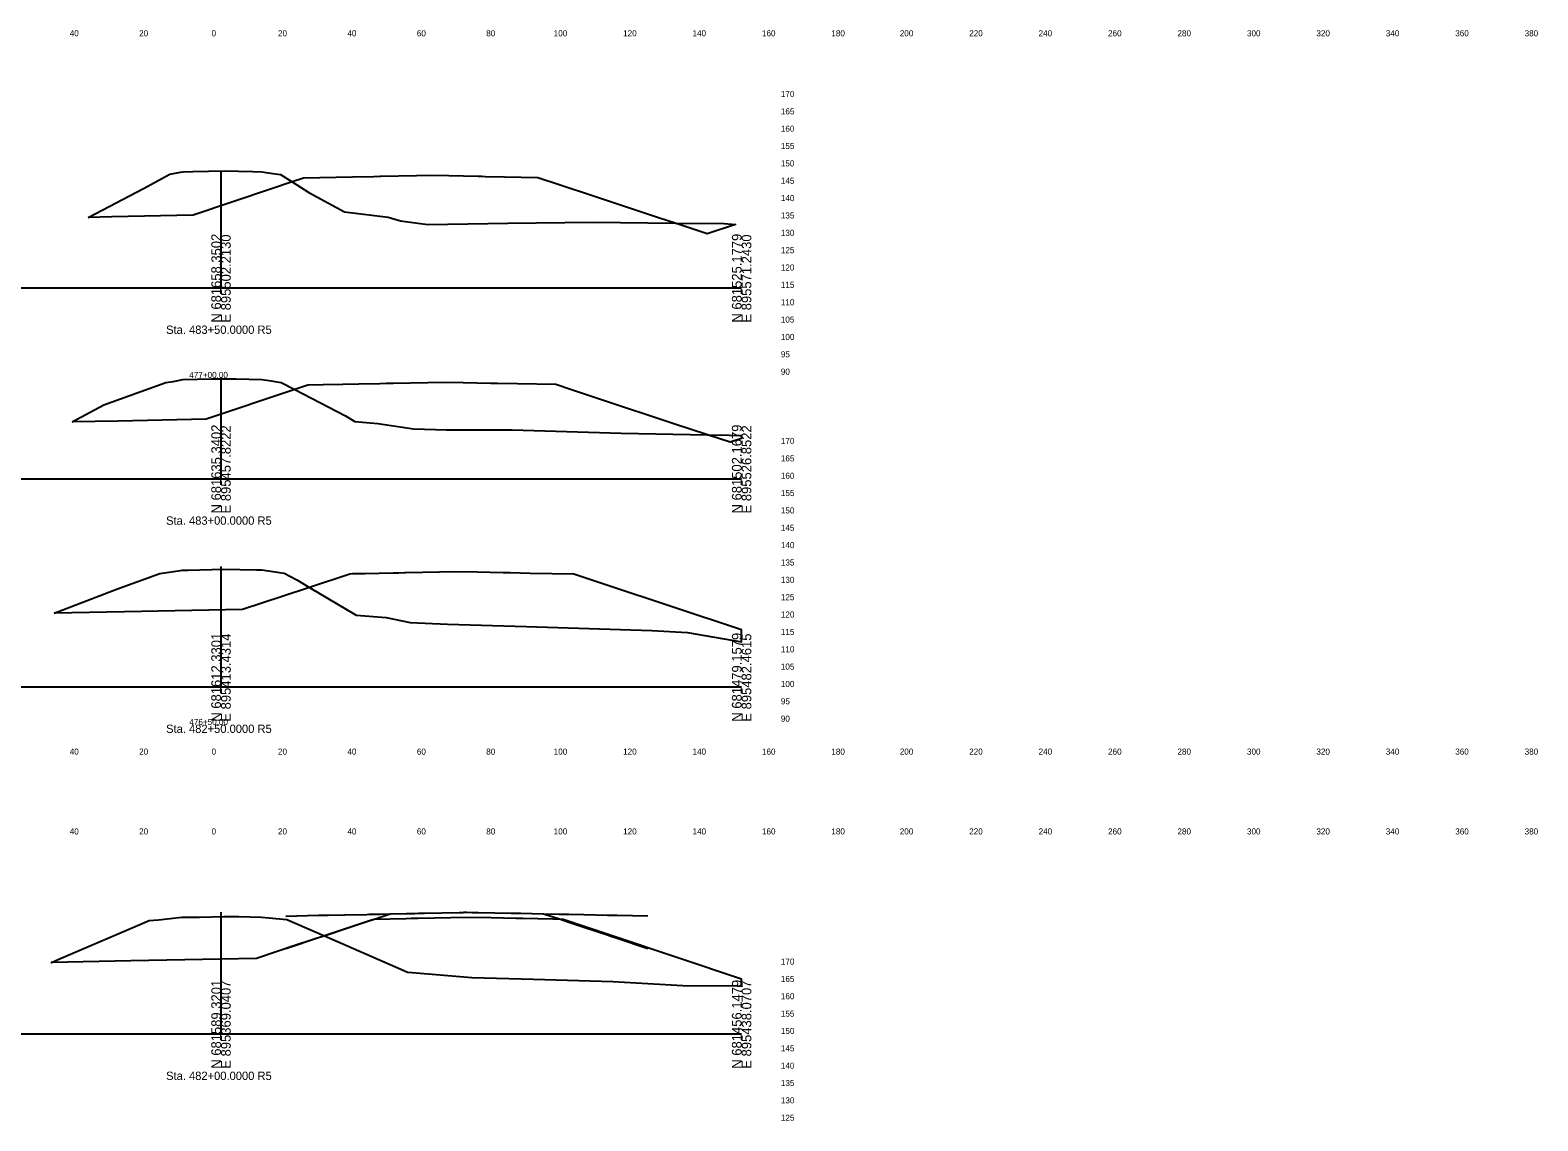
# Model space of a CAD drawing. Extents: x 21059 to 22955, y 6470 to 17494.
# Drawn here: x 21589.8 to 22024.2, y 11659.8 to 11974.1 of the extents above; entities that cross this region are included whole.
import ezdxf

# ---------------------------------------------------------------- set-up
doc = ezdxf.new("R2010")
doc.units = 0
for name, color, linetype in [('Draft_XS_Grid', 7, 'Continuous'), ('Draft_XS_Text', 7, 'Continuous'), ('DTM CONTOURS_MAJOR', 7, 'Continuous'), ('SLOPE_STAKES_FILL', 7, 'Continuous'), ('X_PROFILES_1', 7, 'Continuous'), ('XS_P_GROUND_B', 7, 'Continuous'), ('XS_P_TX_CLEARZONE', 7, 'Continuous'), ('XS_SHEET_EW_TX_VOLUME', 7, 'Continuous')]:
    doc.layers.add(name, color=color, linetype=linetype)

msp = doc.modelspace()

# ---------------------------------------------------------------- linework, layer by layer
at = {"layer": 'DTM CONTOURS_MAJOR'}
for p, q in [((21644.84, 11899.84), (21644.84, 11933.7)), ((21494.84, 11899.84), (21644.84, 11899.84)), ((21644.84, 11899.84), (21794.84, 11899.84)), ((21644.84, 11844.84), (21644.84, 11874.1)), ((21494.84, 11844.84), (21644.84, 11844.84)), ((21644.84, 11844.84), (21794.84, 11844.84)), ((21644.84, 11784.84), (21644.84, 11819.51)), ((21494.84, 11784.84), (21644.84, 11784.84)), ((21644.84, 11784.84), (21794.84, 11784.84)), ((21644.84, 11684.84), (21644.84, 11719.92)), ((21494.84, 11684.84), (21644.84, 11684.84)), ((21644.84, 11684.84), (21794.84, 11684.84))]:
    msp.add_line(p, q, dxfattribs=at)
at = {"layer": 'XS_P_TX_CLEARZONE'}
for points in [[(21663.47, 11709.45), (21672.96, 11712.6), (21673.92, 11712.93), (21675.73, 11713.53), (21680.54, 11715.13), (21686.83, 11717.22), (21687.4, 11717.41), (21689.6, 11718.15), (21690.67, 11718.5), (21693.55, 11719.46), (21698.32, 11719.56), (21700.7, 11719.61), (21701.73, 11719.63), (21703.48, 11719.67), (21713.43, 11719.87), (21714.58, 11719.89), (21714.7, 11719.9), (21715.71, 11719.92), (21717.17, 11719.89), (21717.35, 11719.89), (21719, 11719.85), (21728.45, 11719.67), (21729.49, 11719.65), (21731.22, 11719.62), (21737.77, 11719.49), (21742.32, 11717.98), (21744.47, 11717.27), (21745.09, 11717.06), (21749.37, 11715.64), (21756.19, 11713.38), (21757.18, 11713.05), (21758.96, 11712.46), (21767.85, 11709.51)], [(21663.47, 11718.84), (21672.96, 11719.04), (21673.92, 11719.06), (21675.73, 11719.1), (21680.54, 11719.2), (21686.83, 11719.32), (21687.4, 11719.34), (21689.6, 11719.38), (21690.67, 11719.4), (21693.55, 11719.46), (21698.32, 11719.56), (21700.7, 11719.61), (21701.73, 11719.63), (21703.48, 11719.67), (21713.43, 11719.87), (21714.58, 11719.89), (21714.7, 11719.9), (21715.71, 11719.92), (21717.17, 11719.89), (21717.35, 11719.89), (21719, 11719.85), (21728.45, 11719.67), (21729.49, 11719.65), (21731.22, 11719.62), (21737.77, 11719.49), (21742.32, 11719.4), (21744.47, 11719.36), (21745.09, 11719.35), (21749.37, 11719.27), (21756.19, 11719.13), (21757.18, 11719.12), (21758.96, 11719.08), (21767.85, 11718.91)], [(21663.47, 11709.45), (21672.96, 11712.6), (21673.92, 11712.93), (21675.73, 11713.53), (21680.54, 11715.13), (21686.83, 11717.22), (21687.4, 11717.41), (21689.6, 11718.15), (21690.67, 11718.5), (21693.55, 11719.46), (21698.32, 11719.56), (21700.7, 11719.61), (21701.73, 11719.63), (21703.48, 11719.67), (21713.43, 11719.87), (21714.58, 11719.89), (21714.7, 11719.9), (21715.71, 11719.92), (21717.17, 11719.89), (21717.35, 11719.89), (21719, 11719.85), (21728.45, 11719.67), (21729.49, 11719.65), (21731.22, 11719.62), (21737.77, 11719.49), (21742.32, 11717.98), (21744.47, 11717.27), (21745.09, 11717.06), (21749.37, 11715.64), (21756.19, 11713.38), (21757.18, 11713.05), (21758.96, 11712.46), (21767.85, 11709.51)], [(21663.47, 11718.84), (21672.96, 11719.04), (21673.92, 11719.06), (21675.73, 11719.1), (21680.54, 11719.2), (21686.83, 11719.32), (21687.4, 11719.34), (21689.6, 11719.38), (21690.67, 11719.4), (21693.55, 11719.46), (21698.32, 11719.56), (21700.7, 11719.61), (21701.73, 11719.63), (21703.48, 11719.67), (21713.43, 11719.87), (21714.58, 11719.89), (21714.7, 11719.9), (21715.71, 11719.92), (21717.17, 11719.89), (21717.35, 11719.89), (21719, 11719.85), (21728.45, 11719.67), (21729.49, 11719.65), (21731.22, 11719.62), (21737.77, 11719.49), (21742.32, 11719.4), (21744.47, 11719.36), (21745.09, 11719.35), (21749.37, 11719.27), (21756.19, 11719.13), (21757.18, 11719.12), (21758.96, 11719.08), (21767.85, 11718.91)]]:
    msp.add_lwpolyline(points, dxfattribs=at)
at = {"layer": 'XS_SHEET_EW_TX_VOLUME'}
for points in [[(21606.59, 11920.17), (21622.54, 11928.44), (21630.1, 11932.59), (21633.21, 11933.21), (21633.89, 11933.33), (21636.73, 11933.39), (21645.78, 11933.57), (21654, 11933.35), (21656.58, 11933.28), (21660.41, 11932.74), (21662, 11932.48), (21665.35, 11930.37), (21659.35, 11928.36), (21636.81, 11920.83), (21613.4, 11920.32)], [(21665.35, 11930.37), (21670.15, 11927.33), (21680.43, 11921.77), (21693.01, 11920.22), (21696.54, 11919.12), (21704.47, 11918.11), (21727.52, 11918.45), (21752.08, 11918.74), (21775.64, 11918.5), (21771.17, 11919.98), (21752.12, 11926.29), (21742.23, 11929.56), (21736.11, 11931.59), (21726.49, 11931.78), (21720.91, 11931.89), (21719.99, 11931.9), (21718.91, 11931.92), (21710.48, 11932.09), (21704.87, 11932.2), (21701.15, 11932.12), (21690.84, 11931.91), (21690.61, 11931.91), (21688.83, 11931.87), (21682.76, 11931.74), (21668.61, 11931.46)], [(21775.64, 11918.5), (21789.81, 11918.35), (21793.1, 11918.14), (21784.91, 11915.43)], [(21601.94, 11861.21), (21611.03, 11866.13), (21628.94, 11872.56), (21631.04, 11872.87), (21633.87, 11873.43), (21642.08, 11873.59), (21645.75, 11873.68), (21649.17, 11873.62), (21656.6, 11873.42), (21658.68, 11873.11), (21662.13, 11872.62), (21666.1, 11870.55), (21640.52, 11862.01), (21615.2, 11861.48)], [(21666.1, 11870.55), (21680.74, 11862.94), (21683.41, 11861.36), (21690.04, 11860.78), (21700.32, 11859.26), (21709.79, 11858.94), (21728.77, 11858.95), (21760.15, 11857.97), (21785.01, 11857.49), (21775.3, 11860.7), (21753.92, 11867.78), (21745.52, 11870.57), (21741.31, 11871.96), (21730.22, 11872.17), (21724.53, 11872.28), (21723.65, 11872.3), (21722.52, 11872.32), (21714.56, 11872.48), (21708.49, 11872.6), (21704.46, 11872.51), (21694.45, 11872.31), (21694.17, 11872.3), (21692.44, 11872.27), (21690.6, 11872.23), (21684.56, 11872.1), (21679.98, 11872.01), (21674.26, 11871.89), (21669.84, 11871.8)], [(21785.01, 11857.49), (21791.28, 11857.36), (21794.84, 11857.32), (21794.84, 11856.44), (21791.51, 11855.34)], [(21596.78, 11806.12), (21615.05, 11813.14), (21627.25, 11817.52), (21633.12, 11818.38), (21633.69, 11818.49), (21635.35, 11818.53), (21645.55, 11818.77), (21655.08, 11818.59), (21656.57, 11818.55), (21662.33, 11817.7), (21663.01, 11817.61), (21666.68, 11815.7), (21670.33, 11813.54), (21662.42, 11810.92), (21651.05, 11807.16), (21617, 11806.51)], [(21670.33, 11813.54), (21683.81, 11805.57), (21692.4, 11804.82), (21699.3, 11803.44), (21710.11, 11802.98), (21732.87, 11802.24), (21768.98, 11801.07), (21779.26, 11800.51), (21794.84, 11797.87), (21794.84, 11801.34), (21755.73, 11814.29), (21746.5, 11817.34), (21733.88, 11817.58), (21728.14, 11817.7), (21727.32, 11817.71), (21726.14, 11817.73), (21718.63, 11817.88), (21712.1, 11818.01), (21707.77, 11817.92), (21698.06, 11817.72), (21697.74, 11817.71), (21696.06, 11817.68), (21694.47, 11817.64), (21686.36, 11817.48), (21682.74, 11817.4), (21681.97, 11817.39)], [(21595.97, 11705.49), (21598.13, 11706.38), (21624.11, 11717.5), (21626.84, 11717.77), (21633.59, 11718.52), (21638.65, 11718.53), (21645.64, 11718.7), (21650.02, 11718.66), (21656.54, 11718.54), (21663.78, 11717.82), (21663.83, 11717.82), (21674.63, 11713.12), (21666.73, 11710.5), (21655.06, 11706.62), (21618.81, 11705.93)], [(21674.63, 11713.12), (21696.64, 11703.55), (21698.59, 11702.67), (21699.94, 11702.54), (21717.12, 11701.14), (21734.91, 11700.67), (21757.75, 11699.94), (21777.9, 11698.82), (21793.52, 11698.7), (21794.84, 11698.62), (21794.84, 11700.63), (21757.53, 11713.16), (21743.46, 11717.88), (21740.45, 11717.94), (21731.76, 11718.11), (21730.99, 11718.12), (21729.75, 11718.15), (21722.7, 11718.28), (21715.71, 11718.42), (21711.08, 11718.32), (21701.68, 11718.13), (21701.3, 11718.12), (21699.67, 11718.09), (21698.15, 11718.06), (21688.9, 11717.87), (21688.17, 11717.62)], [(21595.92, 11705.49), (21595.92, 11705.47), (21595.97, 11705.49)]]:
    msp.add_lwpolyline(points, close=True, dxfattribs=at)

# ---------------------------------------------------------------- texts
at = {"layer": 'Draft_XS_Grid'}
for s, p in [('  170  ', (21804.84, 11954.84)), ('  165  ', (21804.84, 11949.84)), ('  160  ', (21804.84, 11944.84)), ('  155  ', (21804.84, 11939.84)), ('  150  ', (21804.84, 11934.84)), ('  145  ', (21804.84, 11929.84)), ('  140  ', (21804.84, 11924.84)), ('  135  ', (21804.84, 11919.84)), ('  130  ', (21804.84, 11914.84)), ('  125  ', (21804.84, 11909.84)), ('  120  ', (21804.84, 11904.84)), ('  115  ', (21804.84, 11899.84)), ('  110  ', (21804.84, 11894.84)), ('  105  ', (21804.84, 11889.84)), ('  100  ', (21804.84, 11884.84)), ('  95  ', (21804.84, 11879.84)), ('  90  ', (21804.84, 11874.84)), ('  170  ', (21804.84, 11854.84)), ('  165  ', (21804.84, 11849.84)), ('  160  ', (21804.84, 11844.84)), ('  155  ', (21804.84, 11839.84)), ('  150  ', (21804.84, 11834.84)), ('  145  ', (21804.84, 11829.84)), ('  140  ', (21804.84, 11824.84)), ('  135  ', (21804.84, 11819.84)), ('  130  ', (21804.84, 11814.84)), ('  125  ', (21804.84, 11809.84)), ('  120  ', (21804.84, 11804.84)), ('  115  ', (21804.84, 11799.84)), ('  110  ', (21804.84, 11794.84)), ('  105  ', (21804.84, 11789.84)), ('  100  ', (21804.84, 11784.84)), ('  95  ', (21804.84, 11779.84)), ('  90  ', (21804.84, 11774.84)), ('  170  ', (21804.84, 11704.84)), ('  165  ', (21804.84, 11699.84)), ('  160  ', (21804.84, 11694.84)), ('  155  ', (21804.84, 11689.84)), ('  150  ', (21804.84, 11684.84)), ('  145  ', (21804.84, 11679.84)), ('  140  ', (21804.84, 11674.84)), ('  135  ', (21804.84, 11669.84)), ('  130  ', (21804.84, 11664.84)), ('  125  ', (21804.84, 11659.84))]:
    msp.add_text(s, height=1.75, dxfattribs=at).set_placement(p)
at = {"layer": 'Draft_XS_Text'}
for s, p in [('  40  ', (21599.95, 11972.34)), ('  20  ', (21619.95, 11972.34)), ('  0  ', (21640.81, 11972.34)), ('  0  ', (21640.81, 11972.34)), ('  20  ', (21659.95, 11972.34)), ('  40  ', (21679.95, 11972.34)), ('  60  ', (21699.97, 11972.34)), ('  80  ', (21719.95, 11972.34)), ('  100  ', (21739.39, 11972.34)), ('  120  ', (21759.39, 11972.34)), ('  140  ', (21779.39, 11972.34)), ('  160  ', (21799.4, 11972.34)), ('  180  ', (21819.39, 11972.34)), ('  200  ', (21839.1, 11972.34)), ('  220  ', (21859.1, 11972.34)), ('  240  ', (21879.1, 11972.34)), ('  260  ', (21899.11, 11972.34)), ('  280  ', (21919.1, 11972.34)), ('  300  ', (21939.13, 11972.34)), ('  320  ', (21959.13, 11972.34)), ('  340  ', (21979.13, 11972.34)), ('  360  ', (21999.14, 11972.34)), ('  380  ', (22019.13, 11972.34)), ('  40  ', (21599.95, 11765.34)), ('  20  ', (21619.95, 11765.34)), ('  0  ', (21640.81, 11765.34)), ('  0  ', (21640.81, 11765.34)), ('  20  ', (21659.95, 11765.34)), ('  40  ', (21679.95, 11765.34)), ('  60  ', (21699.97, 11765.34)), ('  80  ', (21719.95, 11765.34)), ('  100  ', (21739.39, 11765.34)), ('  120  ', (21759.39, 11765.34)), ('  140  ', (21779.39, 11765.34)), ('  160  ', (21799.4, 11765.34)), ('  180  ', (21819.39, 11765.34)), ('  200  ', (21839.1, 11765.34)), ('  220  ', (21859.1, 11765.34)), ('  240  ', (21879.1, 11765.34)), ('  260  ', (21899.11, 11765.34)), ('  280  ', (21919.1, 11765.34)), ('  300  ', (21939.13, 11765.34)), ('  320  ', (21959.13, 11765.34)), ('  340  ', (21979.13, 11765.34)), ('  360  ', (21999.14, 11765.34)), ('  380  ', (22019.13, 11765.34)), ('  40  ', (21599.95, 11742.34)), ('  20  ', (21619.95, 11742.34)), ('  0  ', (21640.81, 11742.34)), ('  0  ', (21640.81, 11742.34)), ('  20  ', (21659.95, 11742.34)), ('  40  ', (21679.95, 11742.34)), ('  60  ', (21699.97, 11742.34)), ('  80  ', (21719.95, 11742.34)), ('  100  ', (21739.39, 11742.34)), ('  120  ', (21759.39, 11742.34)), ('  140  ', (21779.39, 11742.34)), ('  160  ', (21799.4, 11742.34)), ('  180  ', (21819.39, 11742.34)), ('  200  ', (21839.1, 11742.34)), ('  220  ', (21859.1, 11742.34)), ('  240  ', (21879.1, 11742.34)), ('  260  ', (21899.11, 11742.34)), ('  280  ', (21919.1, 11742.34)), ('  300  ', (21939.13, 11742.34)), ('  320  ', (21959.13, 11742.34)), ('  340  ', (21979.13, 11742.34)), ('  360  ', (21999.14, 11742.34)), ('  380  ', (22019.13, 11742.34))]:
    msp.add_text(s, height=1.75, dxfattribs=at).set_placement(p)
at = {"layer": 'DTM CONTOURS_MAJOR'}
for s, p in [('N 681658.3502', (21644.84, 11889.84)), ('E 895502.2130', (21647.64, 11889.84)), ('N 681525.1779', (21794.84, 11889.84)), ('E 895571.2430', (21797.64, 11889.84)), ('N 681635.3402', (21644.84, 11834.84)), ('E 895457.8222', (21647.64, 11834.84)), ('N 681502.1679', (21794.84, 11834.84)), ('E 895526.8522', (21797.64, 11834.84)), ('N 681612.3301', (21644.84, 11774.84)), ('E 895413.4314', (21647.64, 11774.84)), ('N 681479.1579', (21794.84, 11774.84)), ('E 895482.4615', (21797.64, 11774.84)), ('N 681589.3201', (21644.84, 11674.84)), ('E 895369.0407', (21647.64, 11674.84)), ('N 681456.1479', (21794.84, 11674.84)), ('E 895438.0707', (21797.64, 11674.84))]:
    msp.add_text(s, height=2.8, rotation=90, dxfattribs=at).set_placement(p)
at = {"layer": 'SLOPE_STAKES_FILL'}
for s, p in [('  477+00.00  ', (21634.4, 11873.89)), ('  476+50.00  ', (21634.41, 11773.89))]:
    msp.add_text(s, height=1.75, dxfattribs=at).set_placement(p)
at = {"layer": 'X_PROFILES_1'}
for s, p in [('Sta. 483+50.0000 R5', (21629.02, 11886.59)), ('Sta. 483+00.0000 R5', (21629.02, 11831.59)), ('Sta. 482+50.0000 R5', (21629.02, 11771.59)), ('Sta. 482+00.0000 R5', (21629.02, 11671.59))]:
    msp.add_text(s, height=2.4, dxfattribs=at).set_placement(p)
at = {"layer": 'XS_P_GROUND_B'}
for p in [(21636.77, 11920.77), (21636.77, 11920.77), (21784.87, 11915.37), (21784.87, 11915.37), (21640.48, 11861.95), (21640.48, 11861.95), (21791.47, 11855.28), (21791.47, 11855.28), (21651.01, 11807.1), (21651.01, 11807.1), (21655.02, 11706.56), (21655.02, 11706.56)]:
    msp.add_text('X', height=0.12, dxfattribs=at).set_placement(p)

doc.saveas('drawing.dxf')
